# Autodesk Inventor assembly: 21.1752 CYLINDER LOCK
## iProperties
Created: 2007-03
Part Number: 21.1752 CYLINDER LOCK
Document SubType Name: Assembly
Designer: Andy Moles
Translation Standard: STEP AP203
File Name: 1048-U06_ASM
Preprocessor: PRO/ENGINEER BY PARAMETRIC TECHNOLOGY CORPORATION, 2001390
Postprocessor: Build: 344b, Release: 11 SP2 - Date: Fri 08/18/2006
Sent Units: MILLIMETERS
Uncertainty: 0.01002695013386
Author: Andy Moles
